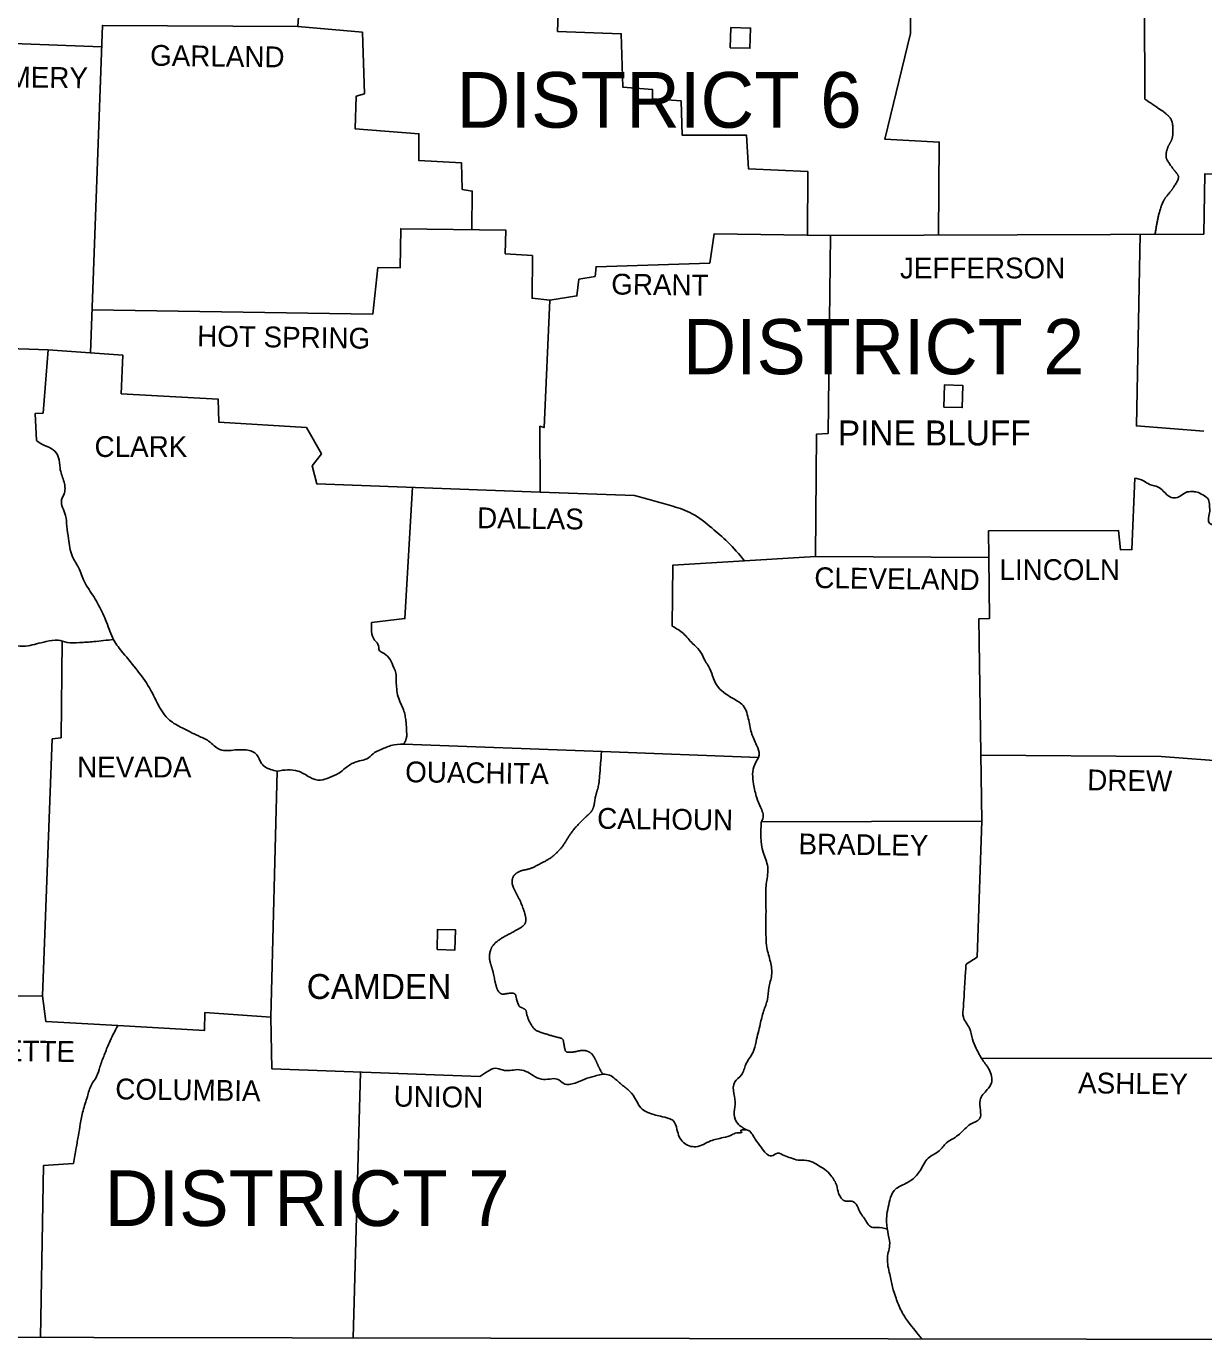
# Model space of a CAD drawing. Extents: x -0.25 to 1.92, y 0 to 0.95.
# Drawn here: x 1.1566 to 1.2668, y 0.5736 to 0.6965 of the extents above; entities that cross this region are included whole.
import ezdxf

# ---------------------------------------------------------------- set-up
doc = ezdxf.new("R2010")
doc.units = 0
doc.layers.add('Default', color=7, linetype='Continuous')

msp = doc.modelspace()

# ---------------------------------------------------------------- linework, layer by layer
at = {"layer": 'Default'}
for points in [[(1.25468, 0.71544), (1.25476, 0.70736), (1.26121, 0.70723), (1.26127, 0.68967)], [(1.23665, 0.7134), (1.2393, 0.71325), (1.23935, 0.69579), (1.23697, 0.68591), (1.24205, 0.68565), (1.24197, 0.67695)], [(1.19734, 0.70186), (1.18245, 0.7023), (1.18204, 0.69644), (1.16375, 0.69655), (1.16263, 0.66592)], [(1.2011, 0.70204), (1.20654, 0.70171), (1.20634, 0.696), (1.2123, 0.69577), (1.21243, 0.69079), (1.21523, 0.69056), (1.21523, 0.6897), (1.2179, 0.68949), (1.21798, 0.6863), (1.224, 0.6863), (1.22421, 0.68314), (1.22976, 0.68288), (1.22973, 0.67694)], [(1.18204, 0.69644), (1.18808, 0.69592), (1.18826, 0.69017), (1.18751, 0.68993), (1.18741, 0.68687), (1.19337, 0.68643), (1.19337, 0.68392), (1.19734, 0.68371), (1.19742, 0.68122), (1.19835, 0.68106), (1.19832, 0.67745)], [(1.14552, 0.69525), (1.16368, 0.69454)], [(1.28417, 0.68218), (1.26689, 0.68267), (1.26679, 0.67704), (1.23188, 0.67691)], [(1.16278, 0.66994), (1.18904, 0.66955), (1.18953, 0.67391), (1.19161, 0.67388), (1.19166, 0.67754), (1.20149, 0.67741), (1.20144, 0.6752), (1.20398, 0.67502), (1.20395, 0.67103), (1.20561, 0.67087)], [(1.20561, 0.67087), (1.20815, 0.67126), (1.20833, 0.67282), (1.20984, 0.67308), (1.20994, 0.67398), (1.22057, 0.67432), (1.22099, 0.67707), (1.23188, 0.67691)], [(1.26084, 0.67702), (1.26049, 0.6591), (1.26679, 0.6586)], [(1.23188, 0.67691), (1.23165, 0.6584), (1.23056, 0.65832), (1.23046, 0.64688)], [(1.20561, 0.67087), (1.20507, 0.65894), (1.20468, 0.65907), (1.2047, 0.65291)], [(1.15867, 0.6662), (1.13222, 0.66711), (1.11466, 0.66714), (1.11427, 0.66192), (1.11489, 0.66148), (1.11487, 0.65562), (1.10171, 0.65622)], [(1.15758, 0.65772), (1.15745, 0.66024), (1.1582, 0.66029), (1.15867, 0.6662), (1.16567, 0.66571), (1.16552, 0.66211), (1.17457, 0.66161), (1.17465, 0.65943), (1.18284, 0.65894), (1.18424, 0.65648), (1.18339, 0.65536), (1.1838, 0.65368), (1.2047, 0.65291)], [(1.26033, 0.65422), (1.26007, 0.64753), (1.25901, 0.6475), (1.2588, 0.64932), (1.24666, 0.64929), (1.24669, 0.6468)], [(1.19278, 0.65335), (1.19205, 0.64107), (1.18894, 0.64071)], [(1.2047, 0.65291), (1.21355, 0.65259)], [(1.22382, 0.64648), (1.21713, 0.64608), (1.21707, 0.64037)], [(1.23046, 0.64688), (1.22382, 0.64648)], [(1.23046, 0.64688), (1.24669, 0.6468)], [(1.24669, 0.6468), (1.24674, 0.64107), (1.24576, 0.64105), (1.24604, 0.62211)], [(1.15999, 0.63897), (1.15989, 0.62992), (1.15906, 0.62982), (1.15815, 0.60578)], [(1.19194, 0.62934), (1.21051, 0.62865), (1.22514, 0.62808)], [(1.24595, 0.62831), (1.26282, 0.62816), (1.27597, 0.62717)], [(1.18009, 0.62681), (1.1795, 0.60378), (1.17335, 0.60422), (1.1733, 0.60253), (1.16519, 0.603)], [(1.2254, 0.62206), (1.24604, 0.62211)], [(1.24604, 0.62211), (1.2456, 0.60941), (1.24456, 0.60876)], [(1.12566, 0.61083), (1.12576, 0.5739), (1.29301, 0.57362)], [(1.16519, 0.603), (1.15846, 0.60339), (1.15815, 0.60578), (1.14433, 0.60565)], [(1.19908, 0.59823), (1.17962, 0.59896), (1.1795, 0.60378)], [(1.24603, 0.59991), (1.276, 0.59994)], [(1.1879, 0.59865), (1.18721, 0.5738)], [(1.16106, 0.59011), (1.15825, 0.58993), (1.15795, 0.57385)]]:
    msp.add_lwpolyline(points, dxfattribs=at)
for points in [[(1.22249, 0.69447), (1.22255, 0.69636), (1.22439, 0.69631), (1.22434, 0.69442)], [(1.24249, 0.66086), (1.24254, 0.66294), (1.24425, 0.66288), (1.2442, 0.66081)], [(1.19506, 0.61011), (1.19511, 0.612), (1.19679, 0.61195), (1.19674, 0.61006)]]:
    msp.add_lwpolyline(points, close=True, dxfattribs=at)
for points in [[(1.26127, 0.68967), (1.26136, 0.68961), (1.26146, 0.68955), (1.26156, 0.68948), (1.26165, 0.68942), (1.26175, 0.68936), (1.26184, 0.68929), (1.26203, 0.68916), (1.26222, 0.68903), (1.26241, 0.6889), (1.26251, 0.68883), (1.26261, 0.68876), (1.26271, 0.68869), (1.26281, 0.68863), (1.26291, 0.68856), (1.26301, 0.68849), (1.26311, 0.68842), (1.2632, 0.68834), (1.26329, 0.68826), (1.26334, 0.68822), (1.26339, 0.68818), (1.26344, 0.68813), (1.26346, 0.68811), (1.26348, 0.68809), (1.2635, 0.68806), (1.26353, 0.68804), (1.26355, 0.68801), (1.26357, 0.68799), (1.26365, 0.6879), (1.26371, 0.68781), (1.26376, 0.68771), (1.2638, 0.68761), (1.26384, 0.68751), (1.26386, 0.6874), (1.26387, 0.6873), (1.26389, 0.68719), (1.2639, 0.68708), (1.2639, 0.68703), (1.2639, 0.68698), (1.26391, 0.68693), (1.26391, 0.68687), (1.26391, 0.68682), (1.26391, 0.68677), (1.26391, 0.6867), (1.26391, 0.68663), (1.26391, 0.68655), (1.26391, 0.68648), (1.2639, 0.68641), (1.26389, 0.68634), (1.26389, 0.68627), (1.26387, 0.6862), (1.26386, 0.68612), (1.26385, 0.68605), (1.26383, 0.68598), (1.26381, 0.68591), (1.26379, 0.68585), (1.26376, 0.68578), (1.26373, 0.68572), (1.2637, 0.68566), (1.26366, 0.68561), (1.26363, 0.68555), (1.2636, 0.68549), (1.26356, 0.68543), (1.26353, 0.68537), (1.26349, 0.68531), (1.26347, 0.68525), (1.26344, 0.68519), (1.26343, 0.68514), (1.26341, 0.68509), (1.2634, 0.68505), (1.26338, 0.685), (1.26336, 0.68495), (1.26335, 0.6849), (1.26332, 0.6848), (1.2633, 0.6847), (1.26328, 0.6846), (1.26326, 0.6845), (1.26326, 0.6844), (1.26326, 0.6843), (1.26327, 0.68425), (1.26327, 0.6842), (1.26329, 0.68415), (1.2633, 0.68411), (1.26332, 0.68406), (1.26334, 0.68402), (1.26342, 0.68387), (1.26351, 0.68373), (1.2636, 0.6836), (1.26369, 0.68346), (1.26379, 0.68332), (1.26389, 0.68319), (1.26393, 0.68313), (1.26397, 0.68308), (1.26401, 0.68303), (1.26406, 0.68297), (1.2641, 0.68292), (1.26415, 0.68287), (1.26421, 0.68279), (1.26428, 0.68271), (1.26433, 0.68262), (1.26434, 0.68261), (1.26435, 0.6826), (1.26436, 0.68258), (1.26436, 0.68257), (1.26437, 0.68256), (1.26438, 0.68254), (1.26442, 0.68245), (1.26443, 0.68234), (1.26441, 0.68225), (1.26439, 0.68214), (1.26435, 0.68202), (1.26429, 0.68193), (1.26419, 0.68176), (1.26409, 0.6816), (1.26398, 0.68145), (1.26395, 0.6814), (1.26392, 0.68135), (1.26389, 0.6813), (1.26385, 0.68125), (1.26382, 0.68119), (1.26378, 0.68114), (1.26375, 0.68109), (1.26371, 0.68105), (1.26367, 0.681), (1.26359, 0.68091), (1.26351, 0.68081), (1.26344, 0.68072), (1.26336, 0.68063), (1.26329, 0.68053), (1.26321, 0.68044), (1.26318, 0.68039), (1.26315, 0.68034), (1.26312, 0.68029), (1.26308, 0.68024), (1.26306, 0.68018), (1.26303, 0.68013), (1.26293, 0.67993), (1.26284, 0.67973), (1.26277, 0.67952), (1.2627, 0.67931), (1.26264, 0.6791), (1.26259, 0.67888), (1.26255, 0.67873), (1.26252, 0.67858), (1.26249, 0.67842), (1.26246, 0.67827), (1.26243, 0.67811), (1.26239, 0.67796), (1.26236, 0.6778), (1.26234, 0.67765), (1.26231, 0.67749), (1.26228, 0.67734), (1.26226, 0.67718), (1.26223, 0.67703)], [(1.21045, 0.62865), (1.21038, 0.62772), (1.2103, 0.62678), (1.21023, 0.62585), (1.21021, 0.62561), (1.21015, 0.62538), (1.21009, 0.62514), (1.21005, 0.62503), (1.21002, 0.62491), (1.20998, 0.6248), (1.20995, 0.62468), (1.20992, 0.62457), (1.20989, 0.62445), (1.20984, 0.62423), (1.20982, 0.62401), (1.20978, 0.62379), (1.20976, 0.62368), (1.20974, 0.62357), (1.20971, 0.62346), (1.20969, 0.62341), (1.20967, 0.62336), (1.20965, 0.62331), (1.20964, 0.62328), (1.20963, 0.62325), (1.20962, 0.62323), (1.20961, 0.6232), (1.20959, 0.62318), (1.20958, 0.62315), (1.20954, 0.62308), (1.20949, 0.62301), (1.20943, 0.62294), (1.20937, 0.62288), (1.20931, 0.62282), (1.20925, 0.62277), (1.20919, 0.62271), (1.20912, 0.62266), (1.20906, 0.6226), (1.209, 0.62254), (1.20894, 0.62249), (1.20888, 0.62243), (1.20876, 0.6223), (1.20864, 0.62218), (1.20852, 0.62205), (1.20839, 0.62192), (1.20827, 0.6218), (1.20815, 0.62167), (1.20791, 0.62143), (1.20771, 0.62115), (1.2075, 0.62087), (1.20745, 0.62079), (1.20739, 0.62071), (1.20734, 0.62063), (1.20729, 0.62054), (1.20724, 0.62046), (1.20719, 0.62038), (1.20714, 0.62029), (1.20709, 0.62021), (1.20704, 0.62013), (1.20699, 0.62004), (1.20694, 0.61996), (1.20688, 0.61988), (1.20671, 0.61964), (1.2065, 0.61942), (1.20629, 0.61921), (1.20605, 0.61898), (1.20581, 0.61876), (1.20553, 0.61859), (1.20527, 0.61843), (1.205, 0.61829), (1.20473, 0.61815), (1.20445, 0.618), (1.20418, 0.61786), (1.2039, 0.61773), (1.20382, 0.6177), (1.20374, 0.61767), (1.20366, 0.61765), (1.20358, 0.61763), (1.2035, 0.61761), (1.20341, 0.61759), (1.20333, 0.61758), (1.20325, 0.61756), (1.20316, 0.61754), (1.20308, 0.61753), (1.203, 0.6175), (1.20291, 0.61747), (1.20278, 0.61743), (1.20266, 0.61737), (1.20254, 0.61729), (1.20248, 0.61726), (1.20243, 0.61722), (1.20238, 0.61717), (1.20236, 0.61714), (1.20233, 0.61712), (1.20231, 0.61709), (1.20228, 0.61706), (1.20226, 0.61704), (1.20224, 0.61701), (1.20218, 0.61692), (1.20215, 0.61683), (1.20212, 0.61674), (1.20209, 0.61664), (1.20208, 0.61654), (1.20208, 0.61645), (1.2021, 0.61626), (1.20214, 0.61607), (1.20221, 0.61589), (1.20227, 0.61576), (1.20233, 0.61563), (1.20239, 0.61551), (1.20246, 0.61538), (1.20253, 0.61526), (1.20259, 0.61513), (1.20266, 0.615), (1.20273, 0.61488), (1.20279, 0.61475), (1.20286, 0.61462), (1.20291, 0.61449), (1.20297, 0.61436), (1.20306, 0.61412), (1.20314, 0.61388), (1.20322, 0.61363), (1.20325, 0.61356), (1.20327, 0.61349), (1.20329, 0.61341), (1.20331, 0.61334), (1.20333, 0.61326), (1.20334, 0.61318), (1.20336, 0.61311), (1.20337, 0.61303), (1.20337, 0.61295), (1.20337, 0.61291), (1.20337, 0.61288), (1.20337, 0.61284), (1.20337, 0.6128), (1.20336, 0.61276), (1.20335, 0.61273), (1.20334, 0.61263), (1.20329, 0.61253), (1.20323, 0.61245), (1.20316, 0.61236), (1.20308, 0.61229), (1.20299, 0.61223), (1.20276, 0.61209), (1.20253, 0.61195), (1.20229, 0.61182), (1.202, 0.61166), (1.2017, 0.61151), (1.20141, 0.61135), (1.20115, 0.61121), (1.2009, 0.61104), (1.20066, 0.61086), (1.20053, 0.61076), (1.20042, 0.61065), (1.20032, 0.61052), (1.20027, 0.61046), (1.20023, 0.6104), (1.20019, 0.61033), (1.20015, 0.61026), (1.20012, 0.61018), (1.20009, 0.61011), (1.20002, 0.60993), (1.19998, 0.60975), (1.19997, 0.60957), (1.19996, 0.6094), (1.19997, 0.60922), (1.20001, 0.60904), (1.20003, 0.60894), (1.20006, 0.60884), (1.20009, 0.60874), (1.20012, 0.60864), (1.20015, 0.60854), (1.20018, 0.60843), (1.20021, 0.60833), (1.20024, 0.60823), (1.20027, 0.60813), (1.2003, 0.60803), (1.20032, 0.60793), (1.20035, 0.60782), (1.2004, 0.60758), (1.20045, 0.60732), (1.2005, 0.60707), (1.20053, 0.60697), (1.20055, 0.60686), (1.20058, 0.60675), (1.2006, 0.60664), (1.20064, 0.60654), (1.20068, 0.60643), (1.20072, 0.60633), (1.20077, 0.60624), (1.20084, 0.60616), (1.20088, 0.60611), (1.20091, 0.60608), (1.20096, 0.60604), (1.20098, 0.60603), (1.201, 0.60601), (1.20102, 0.606), (1.20105, 0.60598), (1.20107, 0.60597), (1.2011, 0.60596), (1.20113, 0.60594), (1.20117, 0.60593), (1.20121, 0.60593), (1.20125, 0.60593), (1.20128, 0.60594), (1.20132, 0.60595), (1.20136, 0.60595), (1.20139, 0.60596), (1.20143, 0.60597), (1.20147, 0.60598), (1.2015, 0.60598), (1.20154, 0.60598), (1.20157, 0.60599), (1.20161, 0.60599), (1.20164, 0.60599), (1.20168, 0.606), (1.20171, 0.606), (1.20175, 0.60601), (1.20182, 0.60602), (1.20189, 0.60603), (1.20195, 0.60604), (1.20202, 0.60605), (1.20209, 0.60605), (1.20216, 0.60603), (1.2022, 0.60603), (1.20223, 0.60602), (1.20227, 0.606), (1.20228, 0.60599), (1.2023, 0.60598), (1.20232, 0.60597), (1.20234, 0.60596), (1.20235, 0.60595), (1.20237, 0.60593), (1.2024, 0.6059), (1.20242, 0.60586), (1.20243, 0.60582), (1.20244, 0.60578), (1.20244, 0.60574), (1.20245, 0.6057), (1.20246, 0.60563), (1.20248, 0.60556), (1.2025, 0.60549), (1.20255, 0.60529), (1.20262, 0.60509), (1.20271, 0.60489), (1.20273, 0.60483), (1.20278, 0.60477), (1.20284, 0.60474), (1.20291, 0.60471), (1.20298, 0.60468), (1.20304, 0.60465), (1.20311, 0.60461), (1.20318, 0.60458), (1.20324, 0.60455), (1.2033, 0.60452), (1.20335, 0.60446), (1.20338, 0.6044), (1.2034, 0.60436), (1.20341, 0.60433), (1.20342, 0.60429), (1.20342, 0.60425), (1.20343, 0.60421), (1.20343, 0.60417), (1.20344, 0.60413), (1.20345, 0.60409), (1.20345, 0.60405), (1.20346, 0.60401), (1.20347, 0.60397), (1.20348, 0.60393), (1.20354, 0.60378), (1.2036, 0.60363), (1.20366, 0.60349), (1.20373, 0.60333), (1.20381, 0.60319), (1.2039, 0.60305), (1.20406, 0.6028), (1.20427, 0.60257), (1.20455, 0.60246), (1.20472, 0.60238), (1.20489, 0.60233), (1.20507, 0.60227), (1.20541, 0.60217), (1.20576, 0.60206), (1.2061, 0.60196), (1.20628, 0.60191), (1.20647, 0.60188), (1.20665, 0.60183), (1.20668, 0.60183), (1.2067, 0.60182), (1.20673, 0.6018), (1.2068, 0.60174), (1.20686, 0.60166), (1.20688, 0.60158), (1.2069, 0.60143), (1.20693, 0.60128), (1.20696, 0.60114), (1.20698, 0.601), (1.20701, 0.60086), (1.20704, 0.60072), (1.20705, 0.60066), (1.20708, 0.60062), (1.20713, 0.60057), (1.20717, 0.60054), (1.20722, 0.60052), (1.20727, 0.60051), (1.20739, 0.6005), (1.20751, 0.6005), (1.20763, 0.60052), (1.20775, 0.60053), (1.20788, 0.60054), (1.208, 0.60056), (1.20808, 0.60058), (1.20817, 0.6006), (1.20826, 0.60062), (1.20834, 0.60064), (1.20843, 0.60065), (1.20852, 0.60067), (1.20867, 0.60069), (1.20883, 0.60068), (1.20899, 0.60065), (1.20907, 0.60063), (1.20914, 0.60061), (1.20922, 0.60057), (1.20926, 0.60055), (1.2093, 0.60053), (1.20933, 0.60051), (1.20937, 0.60049), (1.20941, 0.60046), (1.20945, 0.60043), (1.20954, 0.60036), (1.20962, 0.60028), (1.20968, 0.60018), (1.20974, 0.60008), (1.20979, 0.59999), (1.20984, 0.59989), (1.20988, 0.59981), (1.20992, 0.59974), (1.20995, 0.59966), (1.20999, 0.59958), (1.21002, 0.5995), (1.21006, 0.59942), (1.21009, 0.59934), (1.21013, 0.59927), (1.21016, 0.59919), (1.2102, 0.59911), (1.21024, 0.59903), (1.21028, 0.59896), (1.21037, 0.59879), (1.21044, 0.59862), (1.21056, 0.59848)]]:
    msp.add_open_spline(points, degree=3, dxfattribs=at)
for points in [[(1.15758, 0.65772), (1.15828, 0.65728), (1.15916, 0.65687), (1.15963, 0.65619), (1.15979, 0.65513), (1.16012, 0.65399), (1.1602, 0.65282), (1.15994, 0.65217), (1.1603, 0.65072), (1.16043, 0.64971), (1.16059, 0.64854), (1.16093, 0.64693), (1.16152, 0.64584), (1.16207, 0.64452), (1.16298, 0.64307), (1.16378, 0.64154), (1.16414, 0.64074), (1.16482, 0.63905), (1.16567, 0.63788), (1.16707, 0.63615), (1.16829, 0.63436), (1.16897, 0.63303), (1.17003, 0.63158), (1.17122, 0.63085), (1.17273, 0.6301), (1.17369, 0.62961), (1.17475, 0.62883), (1.17618, 0.62878), (1.17721, 0.62878), (1.1782, 0.62834), (1.17864, 0.62753), (1.17947, 0.62696), (1.18009, 0.62681)], [(1.26033, 0.65422), (1.26116, 0.65396), (1.26173, 0.65362), (1.26254, 0.65337), (1.263, 0.653), (1.26373, 0.65241), (1.26453, 0.65248), (1.2651, 0.65287), (1.2657, 0.65295), (1.26617, 0.6529), (1.26669, 0.65264), (1.26723, 0.6522), (1.26733, 0.65163), (1.26733, 0.65095), (1.26733, 0.64999), (1.26765, 0.64986), (1.26879, 0.64955), (1.26956, 0.6496), (1.27027, 0.6496), (1.27089, 0.64948), (1.27135, 0.64919), (1.27174, 0.64911), (1.27229, 0.64901), (1.27275, 0.64909), (1.27351, 0.64924), (1.27397, 0.64927), (1.27473, 0.64927), (1.27514, 0.64922), (1.27607, 0.64889)], [(1.21355, 0.65259), (1.21713, 0.65158), (1.21894, 0.65088), (1.22076, 0.64955), (1.22226, 0.64823), (1.22382, 0.64648)], [(1.13889, 0.6426), (1.1408, 0.64245), (1.14241, 0.64227), (1.14363, 0.64214), (1.1449, 0.64169), (1.14607, 0.64128), (1.14679, 0.64094), (1.14801, 0.64102), (1.14907, 0.64081), (1.15024, 0.6404), (1.15112, 0.63962), (1.15169, 0.63902), (1.15273, 0.63879), (1.15361, 0.63895), (1.15465, 0.63884), (1.15582, 0.63851), (1.1568, 0.63853), (1.15758, 0.63871), (1.15849, 0.63892), (1.1596, 0.63905), (1.16046, 0.63884), (1.1616, 0.63882), (1.16295, 0.63892), (1.16478, 0.63912)], [(1.18894, 0.64071), (1.18894, 0.63985), (1.18922, 0.63905), (1.18953, 0.63869), (1.18969, 0.63806), (1.1901, 0.6378), (1.19067, 0.63723), (1.19101, 0.63648), (1.19122, 0.63596), (1.19124, 0.63532), (1.19127, 0.63469), (1.19137, 0.63394), (1.19192, 0.63254), (1.19207, 0.632), (1.19215, 0.63153), (1.1922, 0.63075), (1.19218, 0.62984), (1.19194, 0.62934)], [(1.21707, 0.64037), (1.21811, 0.63967), (1.21897, 0.63874), (1.21962, 0.63809), (1.22006, 0.63729), (1.22057, 0.63638), (1.22138, 0.63464), (1.22205, 0.63404), (1.22301, 0.63345), (1.22358, 0.63306), (1.22418, 0.63174), (1.22447, 0.63041), (1.22496, 0.62922), (1.22519, 0.62831), (1.22478, 0.62741), (1.22467, 0.62559), (1.22498, 0.62432), (1.22532, 0.62344), (1.22555, 0.62237), (1.2254, 0.62206)], [(1.18969, 0.62875), (1.19075, 0.62919), (1.19194, 0.62934)], [(1.18969, 0.62875), (1.18922, 0.62855), (1.18865, 0.62805), (1.18795, 0.62779), (1.18733, 0.62761), (1.18647, 0.62707), (1.18587, 0.6266), (1.18499, 0.62621), (1.18416, 0.62595), (1.18315, 0.62624), (1.18261, 0.62655), (1.18204, 0.62681), (1.18009, 0.62681)], [(1.2254, 0.62206), (1.22558, 0.61921), (1.226, 0.61784), (1.22589, 0.61641), (1.22581, 0.61498), (1.22584, 0.61371), (1.22581, 0.61247), (1.22584, 0.6112), (1.22592, 0.61029), (1.22625, 0.60897), (1.22636, 0.60772), (1.2261, 0.60653), (1.22597, 0.60544), (1.22561, 0.60435), (1.2253, 0.60313), (1.22491, 0.60152), (1.22459, 0.60046), (1.22395, 0.59937), (1.22353, 0.59838), (1.22291, 0.59774), (1.22283, 0.59665), (1.22296, 0.59561), (1.22286, 0.5947), (1.22319, 0.59385), (1.224, 0.59325)], [(1.24456, 0.60876), (1.24446, 0.60736), (1.24438, 0.60604), (1.2443, 0.60476), (1.2443, 0.60378), (1.24488, 0.60277), (1.24516, 0.60173), (1.2455, 0.60087), (1.24612, 0.59976), (1.24672, 0.59888), (1.24692, 0.59763), (1.24654, 0.59701), (1.24586, 0.59602), (1.24581, 0.59429), (1.24498, 0.59377), (1.24394, 0.59286), (1.24337, 0.59245), (1.24272, 0.59203), (1.24205, 0.5913), (1.24101, 0.5906), (1.24029, 0.58949), (1.23948, 0.58858), (1.23878, 0.58817), (1.23782, 0.58757), (1.23743, 0.58666), (1.23712, 0.58495), (1.23722, 0.58373), (1.23741, 0.58262), (1.2372, 0.58127), (1.23741, 0.57974), (1.23767, 0.57855), (1.238, 0.57751), (1.2385, 0.57631), (1.23917, 0.57525), (1.24043, 0.57371)], [(1.16106, 0.59011), (1.16129, 0.59156), (1.16152, 0.59273), (1.16168, 0.59379), (1.16194, 0.59504), (1.16235, 0.59636), (1.16272, 0.59745), (1.16321, 0.59823), (1.16352, 0.59914), (1.16393, 0.60025), (1.16438, 0.60137), (1.16519, 0.603)], [(1.19908, 0.59823), (1.19983, 0.59875), (1.2005, 0.59901), (1.2012, 0.59885), (1.2019, 0.5988), (1.20255, 0.59888), (1.20338, 0.59872), (1.20405, 0.59833), (1.20483, 0.598), (1.20561, 0.598), (1.20629, 0.598), (1.20691, 0.59758), (1.20797, 0.59763), (1.2089, 0.598), (1.20981, 0.59828), (1.21106, 0.59841), (1.21212, 0.59766), (1.21292, 0.59701), (1.21355, 0.59628), (1.21401, 0.59545), (1.21453, 0.59499), (1.21534, 0.59468), (1.21598, 0.59452), (1.21674, 0.59431), (1.21715, 0.59411), (1.21751, 0.59328), (1.21811, 0.59206), (1.21928, 0.59167), (1.22065, 0.59221), (1.22182, 0.59252), (1.22265, 0.59278), (1.22312, 0.59296), (1.22358, 0.59304), (1.22348, 0.59312), (1.224, 0.59325), (1.22452, 0.59289), (1.22483, 0.59239), (1.22537, 0.59164), (1.22587, 0.59102), (1.22636, 0.59081), (1.2269, 0.59107), (1.22755, 0.59084), (1.22815, 0.59063), (1.22885, 0.59042), (1.22942, 0.5904), (1.23022, 0.59022), (1.23079, 0.58988), (1.23134, 0.58954), (1.23191, 0.58897), (1.23245, 0.58804), (1.23263, 0.58731), (1.23326, 0.58658), (1.23388, 0.58658), (1.23471, 0.58542), (1.23505, 0.58495), (1.23572, 0.58415), (1.23621, 0.58412), (1.2372, 0.58397)]]:
    msp.add_spline(points, degree=3, dxfattribs=at)

# ---------------------------------------------------------------- texts
for s, rotation, p in [('GARLAND', 359.2717, (1.16821, 0.69279)), ('MONTGOMERY', 359.2707, (1.14317, 0.69092)), ('GRANT', 359.3139, (1.21135, 0.67139)), ('HOT SPRING', 359.1956, (1.17261, 0.66654)), ('DALLAS', 359.2802, (1.1988, 0.64953)), ('CLEVELAND', 359.2412, (1.23035, 0.64393)), ('OUACHITA', 359.2027, (1.19207, 0.62577)), ('DREW', 359.1352, (1.25588, 0.62502)), ('CALHOUN', 359.2686, (1.21003, 0.62142)), ('BRADLEY', 359.2655, (1.22887, 0.61903)), ('LAFAYETTE', 359.2511, (1.1463, 0.59979)), ('ASHLEY', 359.2711, (1.25503, 0.59668)), ('COLUMBIA', 359.2105, (1.16495, 0.59611)), ('UNION', 359.2015, (1.19099, 0.59543))]:
    msp.add_text(s, height=0.001945, rotation=rotation, dxfattribs=at).set_placement(p)
for s, height, p in [('DISTRICT 6', 0.005203, (1.1969, 0.68699)), ('JEFFERSON', 0.001945, (1.23837, 0.67289)), ('DISTRICT 2', 0.005157, (1.21806, 0.66393)), ('PINE BLUFF', 0.002334, (1.23256, 0.65727)), ('CLARK', 0.001945, (1.16302, 0.65619)), ('LINCOLN', 0.001945, (1.24768, 0.64468)), ('NEVADA', 0.001945, (1.16139, 0.62621)), ('CAMDEN', 0.002334, (1.18287, 0.60549)), ('DISTRICT 7', 0.005203, (1.16397, 0.58426))]:
    msp.add_text(s, height=height, dxfattribs=at).set_placement(p)

doc.saveas('drawing.dxf')
